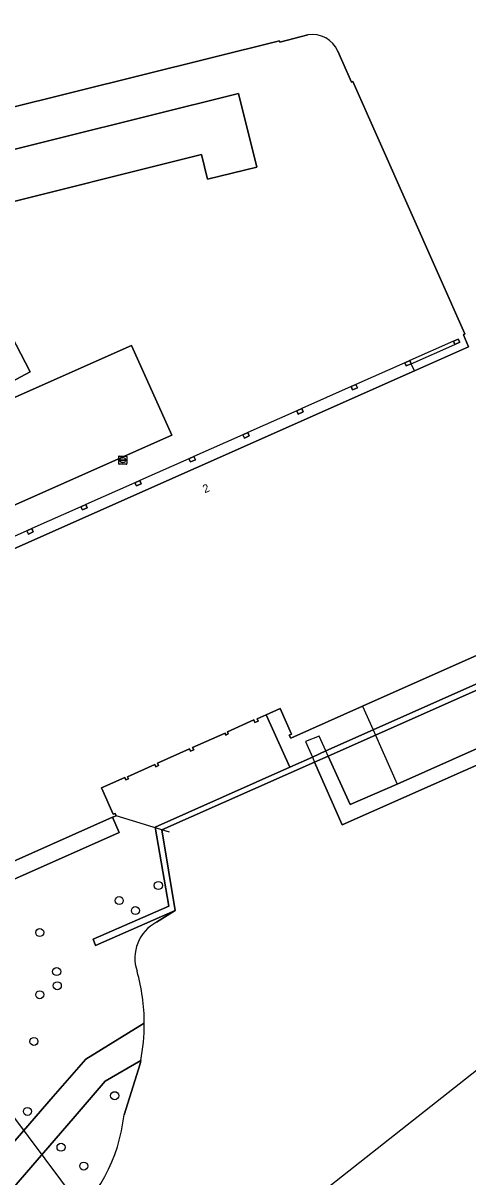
# Model space of a CAD drawing. Extents: x 159499 to 160349, y 382524 to 383273.
# Drawn here: x 160152.8 to 160207.1, y 382789.1 to 382929.6 of the extents above; entities that cross this region are included whole.
import ezdxf

# ---------------------------------------------------------------- set-up
doc = ezdxf.new("R2010")
doc.units = 0
for name, color, linetype in [('IMGEO_Boom', 7, 'Continuous'), ('IMGEO_Dek', 7, 'Continuous'), ('IMGEO_Erf', 7, 'Continuous'), ('IMGEO_Groenvoorziening', 7, 'Continuous'), ('IMGEO_Hek', 7, 'Continuous'), ('IMGEO_Kademuur', 7, 'Continuous'), ('IMGEO_Kolk', 7, 'Continuous'), ('IMGEO_Meer_plas_ven_vijver', 7, 'Continuous'), ('IMGEO_Oever', 7, 'Continuous'), ('IMGEO_Pand', 7, 'Continuous'), ('IMGEO_Pand_nummerreeks', 7, 'Continuous'), ('IMGEO_Pand_overbouw', 7, 'Continuous'), ('IMGEO_Parkeervlak_open', 7, 'Continuous'), ('IMGEO_Voetpad_gesloten', 7, 'Continuous'), ('IMGEO_Voetpad_halfverhard', 7, 'Continuous'), ('IMGEO_Voetpad_open', 7, 'Continuous')]:
    doc.layers.add(name, color=color, linetype=linetype)

msp = doc.modelspace()

# ---------------------------------------------------------------- linework, layer by layer
at = {"layer": 'IMGEO_Boom'}
for centre in [(160169.33, 382824.6), (160164.56, 382822.76), (160166.54, 382821.54), (160154.88, 382818.87), (160156.94, 382814.12), (160154.88, 382811.3), (160157.02, 382812.4), (160154.17, 382805.61), (160164.01, 382799.01), (160153.38, 382797.1), (160157.47, 382792.73), (160160.24, 382790.44)]:
    msp.add_circle(centre, 0.489, dxfattribs=at)
at = {"layer": 'IMGEO_Dek'}
msp.add_lwpolyline([(160240.02, 382853.37), (160236.67, 382861.07), (160236.4, 382861.69), (160235.61, 382863.5), (160233.88, 382862.76), (160234.7, 382860.93), (160234.97, 382860.32), (160237.62, 382854.33), (160231.77, 382851.77), (160198.44, 382836.93), (160192.72, 382834.45), (160190.04, 382840.36), (160189.76, 382840.98), (160188.93, 382842.8), (160187.28, 382842.12), (160188.1, 382840.24), (160188.37, 382839.62), (160191.72, 382831.99)], close=True, dxfattribs=at)
at = {"layer": 'IMGEO_Erf'}
for points in [[(160187.57, 382928.16), (160184.15, 382927.27), (160184.1, 382927.44), (160125.11, 382912.77), (160125.12, 382912.62), (160123.74, 382912.26), (160122.28, 382918.2), (160121.28, 382922.26), (160120.03, 382921.95)], [(160193.02, 382922.48), (160192.86, 382922.42), (160191.21, 382926.19)], [(160151.51, 382892.87), (160149.55, 382891.86), (160150.13, 382890.84), (160151.42, 382891.54), (160153.71, 382887.13), (160137.81, 382878.67), (160143.57, 382867.24), (160143.21, 382867.08), (160143.05, 382867.01), (160142.42, 382866.72), (160144.05, 382863.67), (160142.4, 382862.94), (160142.58, 382862.55), (160142.38, 382862.44), (160142.76, 382861.6), (160147.31, 382863.62), (160200.55, 382887.27), (160207.14, 382890.2), (160206.51, 382891.64), (160206.67, 382891.75), (160193.02, 382922.48)]]:
    msp.add_lwpolyline(points, dxfattribs=at)
for points in [[(160147.62, 382906.86), (160146.12, 382912.84), (160179.1, 382921.04), (160181.32, 382912.06), (160175.32, 382910.59), (160174.58, 382913.58)], [(160166.06, 382890.34), (160170.98, 382879.44), (160146.52, 382868.58), (160141.61, 382879.5)], [(160205.86, 382891.13), (160206.07, 382890.73), (160205.48, 382890.47), (160205.3, 382890.87)], [(160199.98, 382888.5), (160200.15, 382888.11), (160199.55, 382887.85), (160199.39, 382888.24)], [(160193.4, 382885.6), (160193.61, 382885.2), (160193.01, 382884.94), (160192.84, 382885.34)], [(160186.8, 382882.66), (160186.97, 382882.27), (160186.38, 382881.99), (160186.2, 382882.38)], [(160180.24, 382879.74), (160180.41, 382879.36), (160179.82, 382879.08), (160179.64, 382879.47)], [(160173.84, 382876.44), (160173.25, 382876.16), (160173.06, 382876.55), (160173.67, 382876.82)], [(160167.08, 382873.9), (160167.25, 382873.52), (160166.66, 382873.24), (160166.47, 382873.63)], [(160160.67, 382870.6), (160160.08, 382870.32), (160159.9, 382870.71), (160160.5, 382870.98)], [(160154.08, 382867.66), (160153.49, 382867.39), (160153.31, 382867.78), (160153.91, 382868.05)]]:
    msp.add_lwpolyline(points, close=True, dxfattribs=at)
msp.add_arc((160188.13, 382924.85), 3.35, 23.4832, 99.6076, dxfattribs=at)
at = {"layer": 'IMGEO_Groenvoorziening'}
for points in [[(160168.96, 382831.71), (160185.35, 382839.02), (160182.46, 382845.37), (160181.37, 382844.88), (160181.49, 382844.61), (160181.11, 382844.44), (160180.97, 382844.75), (160177.74, 382843.31), (160177.86, 382843.05), (160177.57, 382842.92), (160177.47, 382843.15), (160173.51, 382841.39), (160173.64, 382841.11), (160173.27, 382840.95), (160173.14, 382841.24), (160169.21, 382839.49), (160169.35, 382839.19), (160169.04, 382839.06), (160168.92, 382839.33), (160165.58, 382837.84), (160165.69, 382837.6), (160165.36, 382837.46), (160165.24, 382837.74), (160162.41, 382836.48), (160163.83, 382833.28), (160164.07, 382833.38), (160164.19, 382833.1), (160163.74, 382832.9), (160164.55, 382831.07), (160132.64, 382816.87)], [(160169.12, 382820.12), (160171.4, 382821.57), (160161.68, 382817.31), (160161.39, 382818.08), (160170.61, 382822.07), (160168.96, 382831.71)], [(160139.22, 382805.33), (160140.63, 382803.35), (160148.03, 382793.04), (160151.35, 382792.95), (160156.52, 382798.92), (160160.49, 382803.47), (160167.62, 382807.82)]]:
    msp.add_lwpolyline(points, dxfattribs=at)
for centre, radius, start, end in [((160171.35, 382815.78), 4.88, 117.2128, 199.3634), ((160143.99, 382807.78), 23.63, 0.0865, 15.6599)]:
    msp.add_arc(centre, radius, start, end, dxfattribs=at)
at = {"layer": 'IMGEO_Hek'}
for points in [[(160240.02, 382853.37), (160191.72, 382831.99)], [(160198.44, 382836.93), (160231.77, 382851.77)], [(160190.04, 382840.36), (160192.72, 382834.45)], [(160191.72, 382831.99), (160188.37, 382839.62)], [(160192.72, 382834.45), (160198.44, 382836.93)], [(160170.7, 382831.09), (160164.19, 382833.1)], [(160134.22, 382819.76), (160161.23, 382783.65)]]:
    msp.add_lwpolyline(points, dxfattribs=at)
at = {"layer": 'IMGEO_Kademuur'}
msp.add_lwpolyline([(160251.39, 382868.31), (160236.4, 382861.69), (160234.7, 382860.93), (160228.85, 382858.35), (160195.51, 382843.55), (160189.76, 382840.98), (160188.1, 382840.24), (160185.35, 382839.02), (160168.96, 382831.71), (160170.61, 382822.07), (160161.39, 382818.08), (160161.68, 382817.31), (160171.4, 382821.57), (160169.76, 382831.37), (160188.37, 382839.62), (160190.04, 382840.36), (160195.79, 382842.9), (160229.13, 382857.73)], dxfattribs=at)
at = {"layer": 'IMGEO_Kolk'}
for p, q in [((160164.5, 382875.96), (160164.5, 382876.82)), ((160164.57, 382876.89), (160165.42, 382876.89)), ((160164.75, 382876.38), (160164.75, 382876.4)), ((160165.19, 382876.35), (160164.79, 382876.35)), ((160164.8, 382876.43), (160165.19, 382876.43)), ((160164.98, 382876.67), (160165.01, 382876.67)), ((160165.24, 382876.4), (160165.24, 382876.38)), ((160165.5, 382876.82), (160165.5, 382875.96)), ((160165.42, 382875.89), (160164.57, 382875.89)), ((160165.01, 382876.11), (160164.98, 382876.11))]:
    msp.add_line(p, q, dxfattribs=at)
for points in [[(160164.5, 382875.96), (160164.5, 382876.82)], [(160164.57, 382876.89), (160165.42, 382876.89)], [(160165.5, 382876.82), (160165.5, 382875.96)], [(160165.42, 382875.89), (160164.57, 382875.89)]]:
    msp.add_lwpolyline(points, dxfattribs=at)
for centre, radius, start, end in [((160164.57, 382876.81), 0.0765, 91.552, 178.448), ((160164.57, 382876.81), 0.0765, 91.552, 178.448), ((160164.79, 382876.39), 0.0403, 85.8775, 175.7526), ((160164.79, 382876.38), 0.0366, 178.938, 274.7102), ((160165.2, 382876.39), 0.0386, 1.7309, 96.639), ((160165.2, 382876.39), 0.043, 264.8664, 352.4533), ((160165.42, 382876.81), 0.0765, 1.552, 88.448), ((160165.42, 382876.81), 0.0765, 1.552, 88.448), ((160164.57, 382875.96), 0.0765, 181.552, 268.448), ((160164.57, 382875.96), 0.0765, 181.552, 268.448), ((160165.42, 382875.96), 0.0765, 271.552, 358.448), ((160165.42, 382875.96), 0.0765, 271.552, 358.448)]:
    msp.add_arc(centre, radius, start, end, dxfattribs=at)
for centre, major_axis, ratio, start_param, end_param in [((160164.98, 382876.39), (-0.387, 0.002), 0.722429, 4.712389, 7.853982), ((160165.01, 382876.39), (-0.39, 0.002), 0.717154, 1.570796, 4.712389)]:
    msp.add_ellipse(centre, major_axis=major_axis, ratio=ratio, start_param=start_param, end_param=end_param, dxfattribs=at)
at = {"layer": 'IMGEO_Meer_plas_ven_vijver'}
for points in [[(160251.88, 382867.82), (160236.67, 382861.07), (160234.97, 382860.32), (160229.13, 382857.73), (160195.79, 382842.9), (160190.04, 382840.36), (160188.37, 382839.62), (160169.76, 382831.37), (160171.4, 382821.57), (160169.12, 382820.12)], [(160154.7, 382760.05), (160233.87, 382822.42)], [(160167.19, 382803.28), (160167.11, 382802.9), (160165.15, 382796.68)]]:
    msp.add_lwpolyline(points, dxfattribs=at)
for centre, radius, start, end in [((160171.35, 382815.78), 4.88, 117.2128, 199.3634), ((160143.99, 382807.78), 23.63, 0.0865, 15.6599), ((160143.98, 382807.78), 23.64, 349.0289, 0.0928), ((160144.86, 382798.9), 20.41, 309.432, 353.7421)]:
    msp.add_arc(centre, radius, start, end, dxfattribs=at)
at = {"layer": 'IMGEO_Oever'}
msp.add_lwpolyline([(160165.15, 382796.68), (160167.11, 382802.9), (160167.19, 382803.28), (160162.85, 382800.76), (160158.96, 382796.25), (160151.73, 382787.89), (160152.11, 382787.35), (160152.3, 382787.48), (160153.02, 382786.5), (160152.8, 382786.34), (160151.52, 382785.39), (160148.95, 382783.48), (160148.73, 382783.31), (160150.44, 382780.98)], dxfattribs=at)
msp.add_arc((160144.86, 382798.9), 20.41, 309.432, 353.7421, dxfattribs=at)
at = {"layer": 'IMGEO_Pand'}
for points in [[(160125.9, 382931.22), (160127.05, 382926.62), (160128.12, 382924.66), (160122.52, 382923.25), (160122.48, 382923.42), (160121.08, 382923.06), (160121.28, 382922.26), (160122.28, 382918.2), (160123.74, 382912.26), (160125.12, 382912.62), (160125.11, 382912.77), (160184.1, 382927.44), (160184.15, 382927.27), (160187.57, 382928.16)], [(160191.21, 382926.19), (160192.86, 382922.42), (160193.02, 382922.48), (160206.67, 382891.75), (160206.51, 382891.64), (160207.14, 382890.2), (160200.55, 382887.27), (160147.31, 382863.62)], [(160134.22, 382819.76), (160163.74, 382832.9), (160164.19, 382833.1), (160164.07, 382833.38), (160163.83, 382833.28), (160162.41, 382836.48), (160165.24, 382837.74), (160165.36, 382837.46), (160165.69, 382837.6), (160165.58, 382837.84), (160168.92, 382839.33), (160169.04, 382839.06), (160169.35, 382839.19), (160169.21, 382839.49), (160173.14, 382841.24), (160173.27, 382840.95), (160173.64, 382841.11), (160173.51, 382841.39), (160177.47, 382843.15), (160177.57, 382842.92), (160177.86, 382843.05), (160177.74, 382843.31), (160180.97, 382844.75), (160181.11, 382844.44), (160181.49, 382844.61), (160181.37, 382844.88), (160182.46, 382845.37), (160184.16, 382846.14), (160185.55, 382843.03), (160185.28, 382842.91), (160185.46, 382842.52), (160194.23, 382846.42), (160227.57, 382861.23)]]:
    msp.add_lwpolyline(points, dxfattribs=at)
for points in [[(160146.12, 382912.84), (160147.62, 382906.86), (160174.58, 382913.58), (160175.32, 382910.59), (160181.32, 382912.06), (160179.1, 382921.04)], [(160205.86, 382891.13), (160205.3, 382890.87), (160205.48, 382890.47), (160206.07, 382890.73)], [(160199.98, 382888.5), (160199.39, 382888.24), (160199.55, 382887.85), (160200.15, 382888.11)], [(160193.4, 382885.6), (160192.84, 382885.34), (160193.01, 382884.94), (160193.61, 382885.2)], [(160186.8, 382882.66), (160186.2, 382882.38), (160186.38, 382881.99), (160186.97, 382882.27)], [(160180.24, 382879.74), (160179.64, 382879.47), (160179.82, 382879.08), (160180.41, 382879.36)], [(160173.67, 382876.82), (160173.06, 382876.55), (160173.25, 382876.16), (160173.84, 382876.44)], [(160167.08, 382873.9), (160166.47, 382873.63), (160166.66, 382873.24), (160167.25, 382873.52)], [(160160.5, 382870.98), (160159.9, 382870.71), (160160.08, 382870.32), (160160.67, 382870.6)], [(160153.91, 382868.05), (160153.31, 382867.78), (160153.49, 382867.39), (160154.08, 382867.66)]]:
    msp.add_lwpolyline(points, close=True, dxfattribs=at)
msp.add_arc((160188.13, 382924.85), 3.35, 23.4832, 99.6076, dxfattribs=at)
at = {"layer": 'IMGEO_Pand_overbouw'}
for points in [[(160199.98, 382888.5), (160200.15, 382888.11), (160205.48, 382890.47), (160205.3, 382890.87)], [(160227.57, 382861.23), (160194.23, 382846.42), (160195.51, 382843.55), (160195.79, 382842.9), (160198.44, 382836.93), (160231.77, 382851.77), (160229.13, 382857.73), (160228.85, 382858.35)]]:
    msp.add_lwpolyline(points, close=True, dxfattribs=at)
msp.add_lwpolyline([(160147.31, 382863.62), (160200.55, 382887.27), (160200.15, 382888.11), (160199.55, 382887.85), (160199.39, 382888.24), (160193.4, 382885.6), (160193.61, 382885.2), (160193.01, 382884.94), (160192.84, 382885.34), (160186.8, 382882.66), (160186.97, 382882.27), (160186.38, 382881.99), (160186.2, 382882.38), (160180.24, 382879.74), (160180.41, 382879.36), (160179.82, 382879.08), (160179.64, 382879.47), (160173.67, 382876.82), (160173.84, 382876.44), (160173.25, 382876.16), (160173.06, 382876.55), (160167.08, 382873.9), (160167.25, 382873.52), (160166.66, 382873.24), (160166.47, 382873.63), (160160.5, 382870.98), (160160.67, 382870.6), (160160.08, 382870.32), (160159.9, 382870.71), (160153.91, 382868.05), (160154.08, 382867.66), (160153.49, 382867.39), (160153.31, 382867.78), (160147.34, 382865.14)], dxfattribs=at)
at = {"layer": 'IMGEO_Parkeervlak_open'}
msp.add_lwpolyline([(160227.57, 382861.23), (160194.23, 382846.42), (160185.46, 382842.52), (160185.28, 382842.91), (160185.55, 382843.03), (160184.16, 382846.14), (160182.46, 382845.37), (160185.35, 382839.02), (160188.1, 382840.24), (160189.76, 382840.98), (160195.51, 382843.55), (160228.85, 382858.35)], dxfattribs=at)
at = {"layer": 'IMGEO_Voetpad_gesloten'}
msp.add_lwpolyline([(160240.02, 382853.37), (160236.67, 382861.07), (160236.4, 382861.69), (160235.61, 382863.5), (160233.88, 382862.76), (160234.7, 382860.93), (160234.97, 382860.32), (160237.62, 382854.33), (160231.77, 382851.77), (160198.44, 382836.93), (160192.72, 382834.45), (160190.04, 382840.36), (160189.76, 382840.98), (160188.93, 382842.8), (160187.28, 382842.12), (160188.1, 382840.24), (160188.37, 382839.62), (160191.72, 382831.99)], close=True, dxfattribs=at)
at = {"layer": 'IMGEO_Voetpad_halfverhard'}
msp.add_lwpolyline([(160164.55, 382831.07), (160163.74, 382832.9), (160134.22, 382819.76), (160133.32, 382819.36), (160131.7, 382818.65), (160132.64, 382816.87)], close=True, dxfattribs=at)
msp.add_lwpolyline([(160167.62, 382807.82), (160160.49, 382803.47), (160156.52, 382798.92), (160151.35, 382792.95), (160148.03, 382793.04), (160151.73, 382787.89), (160158.96, 382796.25), (160162.85, 382800.76), (160167.19, 382803.28)], dxfattribs=at)
msp.add_arc((160143.98, 382807.78), 23.64, 349.0289, 0.0928, dxfattribs=at)
at = {"layer": 'IMGEO_Voetpad_open'}
msp.add_lwpolyline([(160140.43, 382896), (160140.75, 382895.4), (160138.18, 382894.02), (160137.49, 382895.33), (160130.78, 382891.75), (160137.81, 382878.67), (160153.71, 382887.13), (160151.42, 382891.54), (160150.13, 382890.84), (160149.55, 382891.86), (160151.51, 382892.87)], dxfattribs=at)
msp.add_lwpolyline([(160146.52, 382868.58), (160170.98, 382879.44), (160166.06, 382890.34), (160141.61, 382879.5)], close=True, dxfattribs=at)

# ---------------------------------------------------------------- texts
at = {"layer": 'IMGEO_Pand_nummerreeks'}
msp.add_text('2', height=1, rotation=23.9496, dxfattribs=at).set_placement((160175, 382872.34))

doc.saveas('drawing.dxf')
